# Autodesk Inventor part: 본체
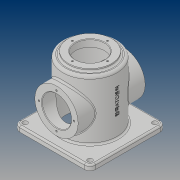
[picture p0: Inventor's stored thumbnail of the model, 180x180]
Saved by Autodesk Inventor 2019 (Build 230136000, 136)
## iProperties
Created: 2019-03
Part Number: 본체
Material: 일반
Document SubType Name: Modeling
Designer: PC312-09
Density: 1 g/cm^3
Appearance: 기본값
Mass: 414.937 g
Surface Area: 1160.05 cm^2
Volume: 414.937 cm^3
Author: PC312-09
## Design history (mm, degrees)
sketch "스케치1"
  geometry: C1 r 50 at (0, 0); 1 further point
  constraints: 1 centre point, 1 coincident
  dimensions: "d0" = 100 diameter of C1
extrude "돌출1" new body sketch "스케치1" distance "d1" = 120; taper "d2" = 0 deg
node "작업 평면1"
sketch "스케치6"
  geometry: C1 r 45 at (0, 0); 1 further point
  constraints: 1 centre point, 1 coincident
  dimensions: "d13" = 90 diameter of C1
extrude "돌출4" cut sketch "스케치6" distance "d14" = 112; taper "d15" = 0 deg
sketch "스케치7"
  geometry: L1 (-70, 70)-(70, 70); L2 (70, 70)-(70, -70); L3 (70, -70)-(-70, -70); L4 (-70, -70)-(-70, 70); L5 (-70, 70)-(70, -70); L6 (70, 70)-(-70, -70); C1 r 45 at (0, 0) reference; 1 further point
  constraints: 12 end point, 2 midpoint, 2 parallel, 1 horizontal, 1 perpendicular
  dimensions: "d16" = 140 distance of L1.start L1.end; "d17" = 140 distance of L1.end L2.end
extrude "돌출5" join sketch "스케치7" distance "d18" = 10; taper "d19" = 0 deg
node "작업 평면2"
sketch "스케치8"
  geometry: L1 (-70, 0)-(70, 0) reference; C1 r 40 at (0, 60); 2 further points
  constraints: 1 centre point, 1 midpoint, 1 vertical alignment
  dimensions: "d21" = 80 diameter of C1; "d22" = 60 distance from line of L1 C1.centre
extrude "돌출6" join sketch "스케치8" stored distance "d23" = 10; taper "d24" = 0 deg
sketch "스케치9"
  geometry: C1 r 40 at (0, 0) reference; C2 r 27 at (0, 0); 1 further point
  constraints: 1 centre point, 1 coincident
  dimensions: "d25" = 54 diameter of C2
extrude "돌출7" cut sketch "스케치9" distance "d26" = 50; taper "d27" = 0 deg
sketch "스케치10" dims "d28" = 65
  geometry: C1 r 27 at (0, 0) reference; 3 further points
  constraints: 2 vertical alignment, 1 coincident, 2 other
hole "구멍1" sketch "스케치10" at (0, 32.5) diameter "d29" = 3.242; stored, may be unused: countersink angle "d33" = 90 deg, drill point angle "d35" = 118 deg; dims "d30" = 8, "d31" = 4, "d32" = 2, "d34" = 10
sketch "스케치11"
  geometry: C1 r 50 at (0, 0) reference; C2 r 40 at (0, 0); 1 further point
  constraints: 1 centre point, 1 coincident
  dimensions: "d39" = 80 diameter of C2
extrude "돌출8" join sketch "스케치11" distance "d40" = 5; taper "d41" = 0 deg
sketch "스케치12"
  geometry: C1 r 40 at (0, 0) reference; C2 r 27 at (0, 0); 1 further point
  constraints: 1 centre point, 1 coincident
  dimensions: "d42" = 54 diameter of C2
extrude "돌출9" cut sketch "스케치12" distance "d43" = 50; taper "d44" = 0 deg
sketch "스케치13" dims "d45" = 65
  geometry: C1 r 50 at (0, 0) reference; 3 further points
  constraints: 2 vertical alignment, 1 coincident, 2 other
hole "구멍2" sketch "스케치13" at (0, 32.5) diameter "d46" = 3.242; stored, may be unused: countersink angle "d50" = 90 deg, drill point angle "d52" = 118 deg; dims "d47" = 8, "d48" = 4, "d49" = 2, "d51" = 10
fillet "모깎기1" dims "d56" = 10
sketch "스케치14"
  geometry: A1 r 10 centre (-60, -60) between (-70, -60) and (-60, -70) reference; A2 r 10 centre (60, -60) between (60, -70) and (70, -60) reference; A3 r 10 centre (60, 60) between (70, 60) and (60, 70) reference; A4 r 10 centre (-60, 60) between (-60, 70) and (-70, 60) reference; 5 further points
  constraints: 4 coincident
hole "구멍3" sketch "스케치14" at (-60, -60), (60, -60), (60, 60), (-60, 60) diameter "d57" = 9; stored, may be unused: countersink angle "d61" = 90 deg, drill point angle "d63" = 0 deg; dims "d58" = 8, "d59" = 4, "d60" = 2, "d62" = 10
fillet "모깎기2" dims "d64" = 3
fillet "모깎기3" dims "d65" = 3
chamfer "모따기1" distance "d67" = 1; stored, may be unused: second distance "d68" = 2, angle "d69" = 45 deg
fillet "모깎기5" dims "d70" = 3
node "작업 평면3"
sketch "스케치15"
  geometry: L1 (0, 60)-(0, -60) reference; 3 further points
  constraints: 1 horizontal alignment, 1 midpoint, 1 other
  dimensions: "d72" = 70 distance from line of L1 point (70, 0)
feature "엠보싱1" sketch "스케치15" dims "d73" = 0.5, "d74" = 0
fillet "모깎기6" dims "d78" = 5
fillet "모깎기7" dims "d79" = 3
node "솔리드1"
pattern_circular "원형 패턴1" dims angle "d37" = 360 deg
mirror "미러1"
pattern_circular "원형 패턴2" dims angle "d54" = 360 deg
other parameters: "d7" = 62, "d20" = 62, "d71" = 51.75
